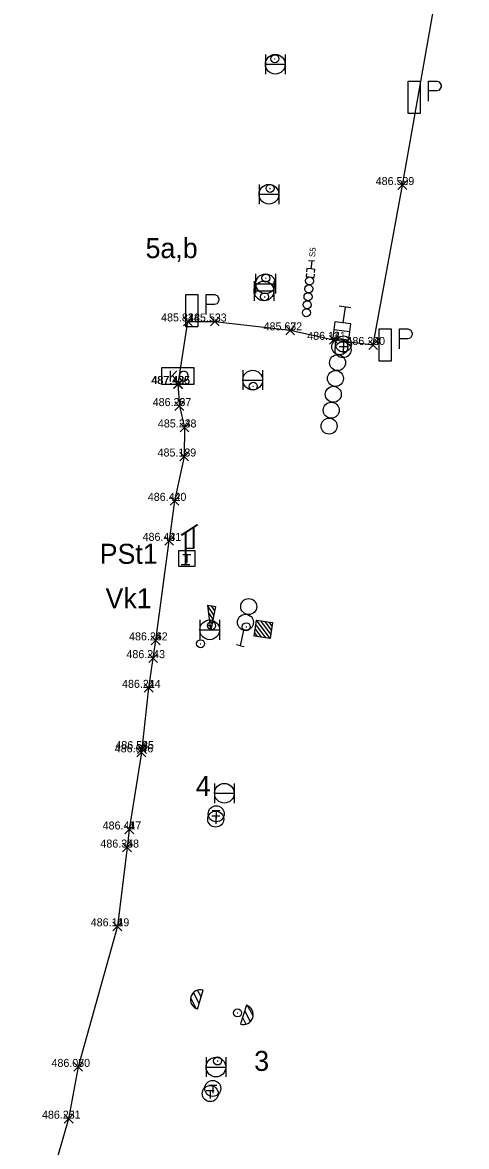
# Model space of a CAD drawing. Extents: x -874058 to -854960, y -10531873 to -1049126.
# Drawn here: x -866565 to -866509.6, y -1050307.6 to -1050167.1 of the extents above; entities that cross this region are included whole.
import ezdxf

# ---------------------------------------------------------------- set-up
doc = ezdxf.new("R2010")
doc.units = 0
for name, color, linetype in [('koleje_osy', 7, 'Continuous'), ('SO_63-33-21_pedestrail', 7, 'Continuous'), ('Vrstva 10', 7, 'Continuous'), ('Vrstva 2', 7, 'Continuous'), ('Vrstva 28', 7, 'Continuous'), ('Vrstva 3', 7, 'Continuous'), ('Vrstva 32', 7, 'Continuous'), ('Vrstva 33', 7, 'Continuous'), ('Vrstva 35', 7, 'Continuous'), ('Vrstva 50', 7, 'Continuous'), ('Vrstva 6', 7, 'Continuous'), ('Vrstva 60', 7, 'Continuous'), ('Vrstva 61', 7, 'Continuous')]:
    doc.layers.add(name, color=color, linetype=linetype)

msp = doc.modelspace()

# ---------------------------------------------------------------- linework, layer by layer
at = {"layer": 'koleje_osy'}
for p, q in [((-866528.52, -1050196.93), (-866529.27, -1050196.86)), ((-866528.89, -1050196.9), (-866528.89, -1050196.9))]:
    msp.add_line(p, q, dxfattribs=at)
for points in [[(-866528.89, -1050196.9), (-866528.99, -1050197.89), (-866529.49, -1050197.84), (-866529.53, -1050198.24)], [(-866529.55, -1050198.46), (-866529.59, -1050198.84), (-866528.6, -1050198.94), (-866528.56, -1050198.56)], [(-866528.54, -1050198.34), (-866528.5, -1050197.94), (-866528.99, -1050197.89)]]:
    msp.add_lwpolyline(points, dxfattribs=at)
for centre in [(-866529.25, -1050200.38), (-866529.15, -1050199.38), (-866529.35, -1050201.37), (-866529.45, -1050202.37), (-866529.55, -1050203.36)]:
    msp.add_circle(centre, 0.5, dxfattribs=at)
at = {"layer": 'Vrstva 10'}
for p, q in [((-866545.18, -1050231.13), (-866543.18, -1050229.83)), ((-866545.13, -1050231.14), (-866543.13, -1050229.84)), ((-866544.68, -1050230.83), (-866544.68, -1050234.83)), ((-866544.63, -1050230.84), (-866544.63, -1050234.84)), ((-866545.18, -1050234.83), (-866544.18, -1050234.83)), ((-866545.13, -1050234.84), (-866544.13, -1050234.84))]:
    msp.add_line(p, q, dxfattribs=at)
for points in [[(-866543.68, -1050230.18), (-866543.68, -1050232.83), (-866544.68, -1050232.83)], [(-866543.63, -1050230.19), (-866543.63, -1050232.84), (-866544.63, -1050232.84)]]:
    msp.add_lwpolyline(points, dxfattribs=at)
at = {"layer": 'Vrstva 28'}
for p, q in [((-866543.59, -1050210.26), (-866547.63, -1050210.26)), ((-866547.63, -1050210.26), (-866547.63, -1050212.28)), ((-866543.59, -1050212.28), (-866543.59, -1050210.26)), ((-866547.63, -1050212.28), (-866543.59, -1050212.28))]:
    msp.add_line(p, q, dxfattribs=at)
msp.add_lwpolyline([(-866541.63, -1050242.99), (-866541.39, -1050242.48), (-866541.82, -1050242.47)], dxfattribs=at)
at = {"layer": 'Vrstva 3'}
for p, q in [((-866534.67, -1050171.08), (-866534.67, -1050173.54)), ((-866532.21, -1050171.08), (-866532.21, -1050173.54)), ((-866534.67, -1050172.31), (-866532.21, -1050172.31)), ((-866535.46, -1050187.32), (-866535.46, -1050189.78)), ((-866535.46, -1050188.55), (-866533, -1050188.55)), ((-866533, -1050187.32), (-866533, -1050189.78)), ((-866536.08, -1050199.41), (-866536.08, -1050201.87)), ((-866535.89, -1050198.52), (-866535.89, -1050200.98)), ((-866535.89, -1050199.75), (-866533.43, -1050199.75)), ((-866533.62, -1050199.41), (-866533.62, -1050201.87)), ((-866533.43, -1050198.52), (-866533.43, -1050200.98)), ((-866536.08, -1050200.64), (-866533.62, -1050200.64)), ((-866525.43, -1050206.87), (-866524.43, -1050206.87)), ((-866524.93, -1050206.87), (-866524.93, -1050207.87)), ((-866525.48, -1050207.59), (-866524.48, -1050207.59)), ((-866524.98, -1050207.59), (-866524.98, -1050208.59)), ((-866537.49, -1050210.55), (-866537.49, -1050213.01)), ((-866535.03, -1050210.55), (-866535.03, -1050213.01)), ((-866537.49, -1050211.78), (-866535.03, -1050211.78)), ((-866541.11, -1050241.14), (-866541.86, -1050240)), ((-866541, -1050240.62), (-866541.42, -1050239.98)), ((-866540.89, -1050240.1), (-866540.9, -1050240.09)), ((-866542.86, -1050241.76), (-866542.86, -1050244.22)), ((-866541.21, -1050241.66), (-866541.76, -1050240.83)), ((-866541.32, -1050242.18), (-866541.66, -1050241.67)), ((-866540.4, -1050241.76), (-866540.4, -1050244.22)), ((-866534.09, -1050244.07), (-866535.77, -1050241.79)), ((-866534.01, -1050243.54), (-866535.25, -1050241.87)), ((-866533.93, -1050243.02), (-866534.72, -1050241.95)), ((-866533.85, -1050242.5), (-866534.2, -1050242.03)), ((-866542.86, -1050242.99), (-866540.4, -1050242.99)), ((-866541.43, -1050242.7), (-866541.56, -1050242.5)), ((-866535.67, -1050243.83), (-866536.01, -1050243.36)), ((-866535.14, -1050243.91), (-866535.93, -1050242.84)), ((-866534.62, -1050243.99), (-866535.85, -1050242.32)), ((-866541.03, -1050262.18), (-866541.03, -1050264.64)), ((-866538.57, -1050262.18), (-866538.57, -1050264.64)), ((-866541.03, -1050263.41), (-866538.57, -1050263.41)), ((-866541.31, -1050265.58), (-866540.31, -1050265.58)), ((-866540.81, -1050265.58), (-866540.81, -1050266.58)), ((-866541.38, -1050266.25), (-866540.38, -1050266.25)), ((-866540.88, -1050266.25), (-866540.88, -1050267.25)), ((-866542.95, -1050289.68), (-866543.66, -1050288.33)), ((-866543.16, -1050290.38), (-866542.44, -1050288.02)), ((-866542.69, -1050288.85), (-866543.14, -1050288.01)), ((-866542.44, -1050288.02), (-866542.44, -1050288.02)), ((-866542.44, -1050288.02), (-866542.44, -1050288.02)), ((-866543.31, -1050290.32), (-866544, -1050289.01)), ((-866537.04, -1050289.9), (-866537.8, -1050292.24)), ((-866537.26, -1050290.59), (-866536.57, -1050291.96)), ((-866536.89, -1050289.96), (-866536.22, -1050291.28)), ((-866537.8, -1050292.24), (-866537.8, -1050292.24)), ((-866537.8, -1050292.24), (-866537.8, -1050292.24)), ((-866537.53, -1050291.42), (-866537.1, -1050292.26)), ((-866542.09, -1050296.41), (-866542.09, -1050298.87)), ((-866539.63, -1050296.41), (-866539.63, -1050298.87)), ((-866542.09, -1050297.64), (-866539.63, -1050297.64)), ((-866542.06, -1050300.55), (-866541.06, -1050300.55)), ((-866541.75, -1050299.9), (-866540.75, -1050299.9)), ((-866541.56, -1050300.55), (-866541.56, -1050301.55)), ((-866541.25, -1050299.9), (-866541.25, -1050300.9))]:
    msp.add_line(p, q, dxfattribs=at)
for points in [[(-866541.49, -1050243.03), (-866541.87, -1050239.89), (-866540.89, -1050240.09), (-866541.49, -1050243.03)], [(-866541.49, -1050243.03), (-866541.87, -1050239.89), (-866540.89, -1050240.09), (-866541.49, -1050243.03)], [(-866536.07, -1050243.77), (-866535.77, -1050241.79), (-866533.79, -1050242.09), (-866534.09, -1050244.07), (-866536.07, -1050243.77)], [(-866536.07, -1050243.77), (-866535.77, -1050241.79), (-866533.79, -1050242.09), (-866534.09, -1050244.07), (-866536.07, -1050243.77)]]:
    msp.add_lwpolyline(points, dxfattribs=at)
msp.add_lwpolyline([(-866536.07, -1050243.77), (-866535.77, -1050241.79), (-866533.79, -1050242.09), (-866534.09, -1050244.07)], close=True, dxfattribs=at)
msp.add_lwpolyline([(-866536.07, -1050243.77), (-866535.77, -1050241.79), (-866533.79, -1050242.09), (-866534.09, -1050244.07)], close=True, dxfattribs=at)
for centre, radius in [((-866533.44, -1050172.31), 1.23), ((-866534.23, -1050188.55), 1.23), ((-866534.85, -1050200.64), 1.23), ((-866534.66, -1050199.75), 1.23), ((-866524.93, -1050207.27), 1), ((-866524.98, -1050207.99), 1), ((-866536.26, -1050211.78), 1.23), ((-866541.63, -1050242.99), 1.23), ((-866539.8, -1050263.41), 1.23), ((-866540.88, -1050266.65), 1), ((-866540.81, -1050265.98), 1), ((-866540.86, -1050297.64), 1.23), ((-866541.25, -1050300.3), 1), ((-866541.56, -1050300.95), 1)]:
    msp.add_circle(centre, radius, dxfattribs=at)
for centre, start, end in [((-866542.8, -1050289.19), 73.0003, 162.9946), ((-866542.8, -1050289.19), 163.0003, 253.0003), ((-866537.42, -1050291.08), 342.0097, 72.0097), ((-866537.42, -1050291.08), 252.0097, 342.0039)]:
    msp.add_arc(centre, 1.23, start, end, dxfattribs=at)
at = {"layer": 'Vrstva 32'}
for points in [[(-866521.22, -1050207.39), (-866517.57, -1050187.41), (-866510.18, -1050145.7), (-866509.56, -1050139.49)], [(-866545.55, -1050212.28), (-866544.37, -1050204.45)], [(-866544.37, -1050204.45), (-866541, -1050204.46), (-866531.57, -1050205.56), (-866526.12, -1050206.75), (-866521.22, -1050207.39)], [(-866545.61, -1050212.28), (-866545.42, -1050215.03), (-866544.77, -1050217.7), (-866544.81, -1050221.33), (-866546.03, -1050226.87), (-866546.68, -1050231.87)], [(-866550.16, -1050258.3), (-866550.08, -1050257.9), (-866549.25, -1050250.24), (-866548.7, -1050246.53), (-866548.37, -1050244.31), (-866546.68, -1050231.87)], [(-866550.16, -1050258.3), (-866551.67, -1050267.94), (-866551.95, -1050270.2), (-866553.16, -1050280.04), (-866558.06, -1050297.61), (-866559.25, -1050304.08), (-866565.01, -1050324.07)]]:
    msp.add_lwpolyline(points, dxfattribs=at)
at = {"layer": 'Vrstva 33'}
for p, q in [((-866544.97, -1050233.59), (-866543.97, -1050233.59)), ((-866544.47, -1050233.59), (-866544.47, -1050234.59))]:
    msp.add_line(p, q, dxfattribs=at)
for points in [[(-866516.84, -1050174.42), (-866515.35, -1050174.42), (-866515.35, -1050178.45), (-866516.84, -1050178.45)], [(-866544.59, -1050201.1), (-866543.1, -1050201.1), (-866543.1, -1050205.13), (-866544.59, -1050205.13)], [(-866520.46, -1050205.39), (-866518.97, -1050205.39), (-866518.97, -1050209.42), (-866520.46, -1050209.42)]]:
    msp.add_lwpolyline(points, close=True, dxfattribs=at)
for points in [[(-866514.3, -1050176.92), (-866514.3, -1050174.41)], [(-866514.3, -1050174.41), (-866513.26, -1050174.41)], [(-866513.26, -1050174.41), (-866512.95, -1050174.51), (-866512.72, -1050174.92), (-866512.72, -1050175.14), (-866512.95, -1050175.56), (-866513.26, -1050175.65)], [(-866513.26, -1050175.65), (-866514.3, -1050175.65)], [(-866542.05, -1050203.6), (-866542.05, -1050201.09)], [(-866542.05, -1050201.09), (-866541.01, -1050201.09)], [(-866541.01, -1050201.09), (-866540.7, -1050201.19), (-866540.47, -1050201.6), (-866540.47, -1050201.82), (-866540.7, -1050202.24), (-866541.01, -1050202.33)], [(-866541.01, -1050202.33), (-866542.05, -1050202.33)], [(-866517.92, -1050207.89), (-866517.92, -1050205.38)], [(-866517.92, -1050205.38), (-866516.88, -1050205.38)], [(-866516.88, -1050205.38), (-866516.57, -1050205.48), (-866516.34, -1050205.89), (-866516.34, -1050206.11), (-866516.57, -1050206.53), (-866516.88, -1050206.62)], [(-866516.88, -1050206.62), (-866517.92, -1050206.62)], [(-866545.47, -1050233.09), (-866543.47, -1050233.09), (-866543.47, -1050235.09), (-866545.47, -1050235.09), (-866545.47, -1050233.09)]]:
    msp.add_lwpolyline(points, dxfattribs=at)
at = {"layer": 'Vrstva 35'}
msp.add_lwpolyline([(-866544.37, -1050204.45), (-866541, -1050204.46), (-866531.57, -1050205.56), (-866526.12, -1050206.75), (-866521.22, -1050207.39)], dxfattribs=at)
at = {"layer": 'Vrstva 50'}
for p, q in [((-866533.54, -1050171.62), (-866533.44, -1050171.62)), ((-866534.14, -1050187.82), (-866534.04, -1050187.82)), ((-866534.66, -1050199.04), (-866534.56, -1050199.04)), ((-866534.82, -1050201.37), (-866534.72, -1050201.37)), ((-866536.24, -1050212.55), (-866536.14, -1050212.55)), ((-866541.44, -1050242.48), (-866541.34, -1050242.48)), ((-866537.11, -1050242.61), (-866537.01, -1050242.61)), ((-866542.82, -1050244.73), (-866542.72, -1050244.73)), ((-866538.2, -1050290.87), (-866538.1, -1050290.87)), ((-866540.69, -1050296.87), (-866540.59, -1050296.87))]:
    msp.add_line(p, q, dxfattribs=at)
for centre in [(-866533.49, -1050171.62), (-866534.09, -1050187.82), (-866534.61, -1050199.04), (-866534.77, -1050201.37), (-866536.19, -1050212.55), (-866541.39, -1050242.48), (-866537.06, -1050242.61), (-866542.77, -1050244.73), (-866538.15, -1050290.87), (-866540.64, -1050296.87)]:
    msp.add_circle(centre, 0.5, dxfattribs=at)
at = {"layer": 'Vrstva 6'}
for p, q in [((-866523.99, -1050202.76), (-866525.47, -1050202.56)), ((-866524.73, -1050202.66), (-866524.73, -1050202.66)), ((-866524.14, -1050205.77), (-866526.12, -1050205.5)), ((-866537.8, -1050244.98), (-866537.38, -1050243.02)), ((-866537.8, -1050244.98), (-866538.29, -1050244.88)), ((-866537.8, -1050244.98), (-866537.31, -1050245.08))]:
    msp.add_line(p, q, dxfattribs=at)
msp.add_lwpolyline([(-866524.73, -1050202.66), (-866525, -1050204.64), (-866525.99, -1050204.51), (-866526.25, -1050206.49), (-866524.27, -1050206.76), (-866524, -1050204.77), (-866525, -1050204.64)], dxfattribs=at)
for centre in [(-866525.39, -1050207.62), (-866525.66, -1050209.6), (-866525.92, -1050211.58), (-866526.19, -1050213.56), (-866526.45, -1050215.55), (-866526.72, -1050217.53), (-866536.76, -1050240.09), (-866537.17, -1050242.05)]:
    msp.add_circle(centre, 1, dxfattribs=at)
at = {"layer": 'Vrstva 60'}
for p, q in [((-866518.12, -1050187.96), (-866517.02, -1050186.86)), ((-866517.02, -1050187.96), (-866518.12, -1050186.86)), ((-866544.92, -1050205), (-866543.82, -1050203.9)), ((-866543.82, -1050205), (-866544.92, -1050203.9)), ((-866541.55, -1050205.01), (-866540.45, -1050203.91)), ((-866540.45, -1050205.01), (-866541.55, -1050203.91)), ((-866532.12, -1050206.11), (-866531.02, -1050205.01)), ((-866531.02, -1050206.11), (-866532.12, -1050205.01)), ((-866526.67, -1050207.3), (-866525.57, -1050206.2)), ((-866525.57, -1050207.3), (-866526.67, -1050206.2)), ((-866521.77, -1050207.94), (-866520.67, -1050206.84)), ((-866520.67, -1050207.94), (-866521.77, -1050206.84)), ((-866546.16, -1050212.83), (-866545.06, -1050211.73)), ((-866545.06, -1050212.83), (-866546.16, -1050211.73)), ((-866546.1, -1050212.83), (-866545, -1050211.73)), ((-866545, -1050212.83), (-866546.1, -1050211.73)), ((-866545.97, -1050215.58), (-866544.87, -1050214.48)), ((-866544.87, -1050215.58), (-866545.97, -1050214.48)), ((-866545.32, -1050218.25), (-866544.22, -1050217.15)), ((-866544.22, -1050218.25), (-866545.32, -1050217.15)), ((-866545.36, -1050221.88), (-866544.26, -1050220.78)), ((-866544.26, -1050221.88), (-866545.36, -1050220.78)), ((-866546.58, -1050227.42), (-866545.48, -1050226.32)), ((-866545.48, -1050227.42), (-866546.58, -1050226.32)), ((-866547.23, -1050232.42), (-866546.13, -1050231.32)), ((-866546.13, -1050232.42), (-866547.23, -1050231.32)), ((-866548.92, -1050244.86), (-866547.82, -1050243.76)), ((-866547.82, -1050244.86), (-866548.92, -1050243.76)), ((-866549.25, -1050247.08), (-866548.15, -1050245.98)), ((-866548.15, -1050247.08), (-866549.25, -1050245.98)), ((-866549.8, -1050250.79), (-866548.7, -1050249.69)), ((-866548.7, -1050250.79), (-866549.8, -1050249.69)), ((-866550.63, -1050258.45), (-866549.53, -1050257.35)), ((-866549.53, -1050258.45), (-866550.63, -1050257.35)), ((-866550.71, -1050258.85), (-866549.61, -1050257.75)), ((-866549.61, -1050258.85), (-866550.71, -1050257.75)), ((-866552.22, -1050268.49), (-866551.12, -1050267.39)), ((-866551.12, -1050268.49), (-866552.22, -1050267.39)), ((-866552.5, -1050270.75), (-866551.4, -1050269.65)), ((-866551.4, -1050270.75), (-866552.5, -1050269.65)), ((-866553.71, -1050280.59), (-866552.61, -1050279.49)), ((-866552.61, -1050280.59), (-866553.71, -1050279.49)), ((-866558.61, -1050298.16), (-866557.51, -1050297.06)), ((-866557.51, -1050298.16), (-866558.61, -1050297.06)), ((-866559.8, -1050304.63), (-866558.7, -1050303.53)), ((-866558.7, -1050304.63), (-866559.8, -1050303.53))]:
    msp.add_line(p, q, dxfattribs=at)

# ---------------------------------------------------------------- texts
at = {"layer": 'SO_63-33-21_pedestrail'}
msp.add_text('S5', height=0.75, rotation=83.7388, dxfattribs=at).set_placement((-866528.49, -1050196.45))
at = {"layer": 'Vrstva 10'}
msp.add_text('PSt1', height=2.5, dxfattribs=at).set_placement((-866555.37, -1050234.74))
at = {"layer": 'Vrstva 2'}
for s, p in [('5a,b', (-866549.64, -1050196.54)), ('Vk1', (-866554.64, -1050240.29)), ('4', (-866543.37, -1050263.75)), ('3', (-866536.07, -1050298.11))]:
    msp.add_text(s, height=2.5, dxfattribs=at).set_placement(p)
at = {"layer": 'Vrstva 28'}
msp.add_text('KO', height=1.344, dxfattribs=at).set_placement((-866546.76, -1050211.96))
at = {"layer": 'Vrstva 60'}
for s, p in [('29', (-866517.57, -1050187.41)), ('34', (-866544.37, -1050204.45)), ('33', (-866541, -1050204.46)), ('32', (-866531.57, -1050205.56)), ('31', (-866526.12, -1050206.75)), ('30', (-866521.22, -1050207.39)), ('36', (-866545.61, -1050212.28)), ('35', (-866545.55, -1050212.28)), ('37', (-866545.42, -1050215.03)), ('38', (-866544.77, -1050217.7)), ('39', (-866544.81, -1050221.33)), ('40', (-866546.03, -1050226.87)), ('41', (-866546.68, -1050231.87)), ('42', (-866548.37, -1050244.31)), ('43', (-866548.7, -1050246.53)), ('44', (-866549.25, -1050250.24)), ('46', (-866550.16, -1050258.3)), ('45', (-866550.08, -1050257.9)), ('47', (-866551.67, -1050267.94)), ('48', (-866551.95, -1050270.2)), ('49', (-866553.16, -1050280.04)), ('50', (-866558.06, -1050297.61)), ('51', (-866559.25, -1050304.08))]:
    msp.add_text(s, height=1, dxfattribs=at).set_placement(p)
at = {"layer": 'Vrstva 61'}
for s, p in [('486.59 ', (-866520.9, -1050187.41)), ('485.81 ', (-866547.7, -1050204.45)), ('485.53 ', (-866544.33, -1050204.46)), ('485.67 ', (-866534.9, -1050205.56)), ('486.14 ', (-866529.45, -1050206.75)), ('486.24 ', (-866524.55, -1050207.39)), ('487.40 ', (-866548.94, -1050212.28)), ('487.42 ', (-866548.88, -1050212.28)), ('486.26 ', (-866548.75, -1050215.03)), ('485.24 ', (-866548.1, -1050217.7)), ('485.18 ', (-866548.14, -1050221.33)), ('486.42 ', (-866549.36, -1050226.87)), ('486.43 ', (-866550.01, -1050231.87)), ('486.26 ', (-866551.7, -1050244.31)), ('486.24 ', (-866552.03, -1050246.53)), ('486.21 ', (-866552.58, -1050250.24)), ('486.64 ', (-866553.49, -1050258.3)), ('486.58 ', (-866553.41, -1050257.9)), ('486.41 ', (-866555, -1050267.94)), ('486.35 ', (-866555.28, -1050270.2)), ('486.11 ', (-866556.49, -1050280.04)), ('486.07 ', (-866561.39, -1050297.61)), ('486.23 ', (-866562.58, -1050304.08))]:
    msp.add_text(s, height=1, dxfattribs=at).set_placement(p)

doc.saveas('drawing.dxf')
